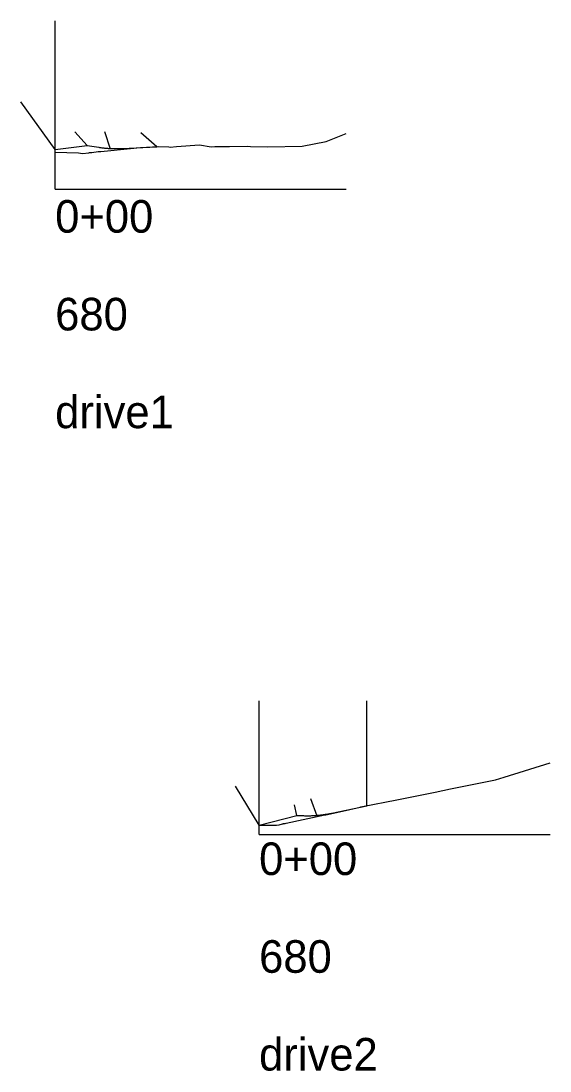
# Model space of a CAD drawing. Extents: x 0 to 3518, y -260 to 220.
# Drawn here: x 367.8 to 549.6, y -259.6 to 101.3 of the extents above; entities that cross this region are included whole.
import ezdxf

# ---------------------------------------------------------------- set-up
doc = ezdxf.new("R2010")
doc.units = 0
for name, color, linetype in [('Default', 7, 'Continuous'), ('MT_P_Work_Area', 7, 'Continuous'), ('PV_P_Shoulder', 7, 'Continuous')]:
    doc.layers.add(name, color=color, linetype=linetype)

msp = doc.modelspace()

# ---------------------------------------------------------------- linework, layer by layer
at = {"layer": 'Default'}
for p, q in [((379.54, 43.43), (379.54, 101.28)), ((379.54, 57.15), (367.79, 73.5)), ((390.54, 58.51), (386.29, 63.15)), ((398.54, 57.26), (396.61, 63.21)), ((414.54, 58.08), (408.94, 62.79)), ((379.54, 43.43), (479.54, 43.43)), ((449.64, -178.36), (449.64, -132.36)), ((486.64, -168.49), (486.64, -132.36)), ((449.64, -175.16), (441.48, -161.77)), ((462.64, -171.78), (461.83, -168.18)), ((469.64, -172.06), (467.46, -166.05)), ((449.64, -178.36), (549.64, -178.36))]:
    msp.add_line(p, q, dxfattribs=at)
at = {"layer": 'MT_P_Work_Area'}
for points in [[(379.54, 56.2), (387.61, 55.94), (388.99, 55.72), (391.16, 56.02), (391.36, 56.09), (391.51, 56.03), (391.58, 56.06), (391.88, 56.07), (392.2, 56.11), (394.3, 56.42), (395.26, 56.47), (406.56, 57.57), (407.56, 57.64), (408.87, 57.82), (415.09, 58.1), (418.62, 58.06), (419.03, 57.95), (421.27, 58.14), (429.18, 58.76), (433.17, 58.08), (434.43, 58.11), (439.47, 58.1), (445.56, 58.26), (446.69, 58.16), (452.59, 58.02), (464.41, 58.2), (472.68, 59.9), (472.75, 59.85), (479.54, 62.6)], [(449.64, -175.1), (453.44, -175.19), (454.98, -175.14), (455.62, -175.1), (456.5, -175.06), (457.65, -174.67), (457.81, -174.66), (457.88, -174.64), (458.05, -174.6), (458.29, -174.57), (458.61, -174.51), (458.95, -174.46), (472.28, -171.63), (472.33, -171.62), (472.41, -171.61), (472.54, -171.59), (478.33, -170.29), (484.43, -168.95), (484.64, -168.88), (485.16, -168.78), (497.04, -166.42), (510.13, -163.81), (515.45, -162.69), (530.88, -159.51), (533.87, -158.66), (549.64, -153.73)]]:
    msp.add_lwpolyline(points, dxfattribs=at)
at = {"layer": 'PV_P_Shoulder'}
for p, q in [((379.54, 57.15), (390.54, 58.51)), ((390.54, 58.51), (394.54, 57.88)), ((402.54, 57.46), (414.54, 58.08)), ((474.64, -171.01), (486.64, -168.49)), ((449.64, -175.16), (462.64, -171.78)), ((462.64, -171.78), (464.64, -171.86))]:
    msp.add_line(p, q, dxfattribs=at)
for points in [[(394.54, 57.88), (398.54, 57.26), (402.54, 57.46)], [(464.64, -171.86), (469.64, -172.06), (474.64, -171.01)]]:
    msp.add_open_spline(points, degree=2, dxfattribs=at)

# ---------------------------------------------------------------- texts
at = {"layer": 'Default'}
for s, p in [('0+00', (379.54, 28.52)), ('680', (379.54, -5.08)), ('drive1', (379.54, -38.68)), ('0+00', (449.64, -192.28)), ('680', (449.64, -225.88)), ('drive2', (449.64, -259.48))]:
    msp.add_text(s, height=11.2, dxfattribs=at).set_placement(p)

doc.saveas('drawing.dxf')
